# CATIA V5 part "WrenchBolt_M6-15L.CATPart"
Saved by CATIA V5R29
Part number: WrenchBolt_M6-15L
Source: Unknown
Bounding box of the stored display mesh (mm): x -5.11 to 5.11, y -5.11 to 5.11, z -15 to 6
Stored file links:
  C:\Users\Administrator\Desktop\프로젝트\Boxfold\TapeCutter\WrenchBolt_M6-15L.CATPart
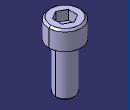
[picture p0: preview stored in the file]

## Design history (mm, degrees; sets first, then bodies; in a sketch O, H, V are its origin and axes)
Body1 (main body)
  Solid1 "PartBody": solid without history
